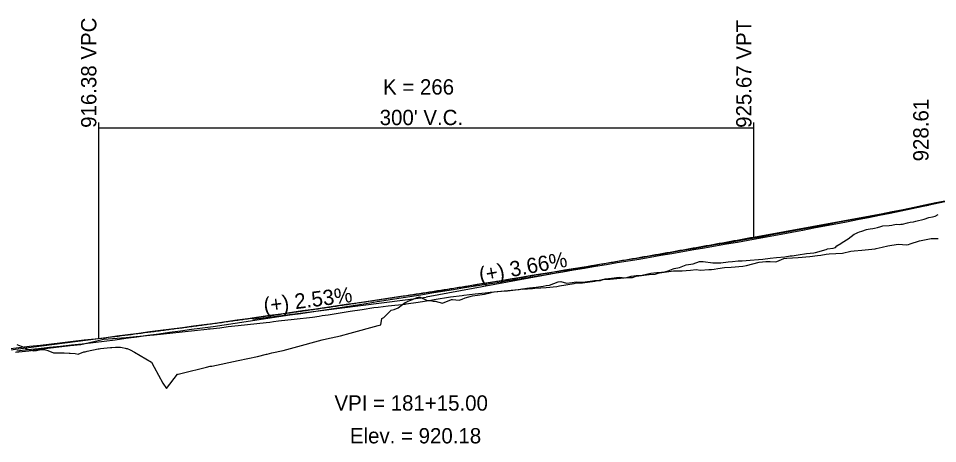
# Model space of a CAD drawing. Extents: x 1475774 to 1484571, y 1098511 to 1113011.
# Drawn here: x 1480699.3 to 1481120.2, y 1104045 to 1104239.7 of the extents above; entities that cross this region are included whole.
import ezdxf

# ---------------------------------------------------------------- set-up
doc = ezdxf.new("R2010")
doc.units = 0
for name, color, linetype in [('RD_DDB_GradeTX', 7, 'Continuous'), ('RD_DDB_PointTX', 7, 'Continuous'), ('RD_DDB_Profile_EX', 7, 'Continuous'), ('RD_DDB_Profile_Lbl', 7, 'Continuous'), ('RD_DDB_Profile_PR', 7, 'Continuous'), ('RD_DDB_StripGrade', 7, 'Continuous'), ('RD_DDB_VCLbl', 7, 'Continuous'), ('RD_Sketch2', 7, 'Continuous'), ('RD_Sketch3', 7, 'Continuous')]:
    doc.layers.add(name, color=color, linetype=linetype)

msp = doc.modelspace()

# ---------------------------------------------------------------- linework, layer by layer
at = {"layer": 'RD_DDB_GradeTX'}
for p in [(1480964.68, 1104126.56), (1480806.62, 1104102.09)]:
    msp.add_line(p, (1480885.98, 1104112.15), dxfattribs=at)
at = {"layer": 'RD_DDB_PointTX'}
msp.add_lwpolyline([(1480694.42, 1104088.43), (1480699.42, 1104089.01), (1480704.42, 1104089.59), (1480709.42, 1104090.16), (1480714.42, 1104090.75), (1480719.42, 1104091.33), (1480724.42, 1104091.91), (1480729.42, 1104092.49), (1480734.42, 1104093.06), (1480739.42, 1104093.68), (1480744.42, 1104094.34), (1480749.42, 1104095), (1480754.42, 1104095.65), (1480759.42, 1104096.31), (1480764.42, 1104096.95), (1480769.42, 1104097.61), (1480774.42, 1104098.27), (1480779.42, 1104098.93), (1480784.42, 1104099.59), (1480789.42, 1104100.24), (1480794.42, 1104100.95), (1480799.42, 1104101.66), (1480804.42, 1104102.38), (1480809.42, 1104103.09), (1480814.42, 1104103.8), (1480819.42, 1104104.51), (1480824.42, 1104105.23), (1480829.42, 1104105.94), (1480834.42, 1104106.66), (1480839.42, 1104107.39), (1480844.42, 1104108.11), (1480849.42, 1104108.84), (1480854.42, 1104109.57), (1480859.42, 1104110.3), (1480864.42, 1104111.04), (1480869.42, 1104111.77), (1480874.42, 1104112.5), (1480879.42, 1104113.22), (1480884.42, 1104113.95), (1480889.42, 1104114.7), (1480894.42, 1104115.52), (1480899.42, 1104116.34), (1480904.42, 1104117.17), (1480909.42, 1104117.99), (1480914.42, 1104118.81), (1480919.42, 1104119.63), (1480924.42, 1104120.45), (1480929.42, 1104121.28), (1480934.42, 1104122.1), (1480939.42, 1104122.92), (1480944.42, 1104123.75), (1480949.42, 1104124.57), (1480954.42, 1104125.39), (1480959.42, 1104126.21), (1480964.42, 1104127.03), (1480969.42, 1104127.85), (1480974.42, 1104128.68), (1480979.42, 1104129.5), (1480984.42, 1104130.32), (1480989.42, 1104131.15), (1480994.42, 1104132.01), (1480999.42, 1104132.87), (1481004.42, 1104133.73), (1481009.42, 1104134.59), (1481014.42, 1104135.45), (1481019.42, 1104136.31), (1481024.42, 1104137.18), (1481029.42, 1104138.04), (1481034.42, 1104138.9), (1481039.42, 1104139.77), (1481044.42, 1104140.72), (1481049.42, 1104141.66), (1481054.42, 1104142.61), (1481059.42, 1104143.55), (1481064.42, 1104144.5), (1481069.42, 1104145.44), (1481074.42, 1104146.38), (1481079.42, 1104147.33), (1481084.42, 1104148.27), (1481089.42, 1104149.24), (1481094.42, 1104150.26), (1481099.42, 1104151.28), (1481104.42, 1104152.31), (1481109.42, 1104153.33), (1481114.42, 1104154.35), (1481119.42, 1104155.38), (1481124.42, 1104156.4)], dxfattribs=at)
at = {"layer": 'RD_DDB_Profile_EX'}
msp.add_lwpolyline([(1480698.54, 1104087.54), (1480703.54, 1104088.07), (1480708.54, 1104088.6), (1480713.54, 1104089.19), (1480718.54, 1104089.72), (1480723.54, 1104090.26), (1480728.54, 1104090.8), (1480733.54, 1104091.34), (1480738.54, 1104091.96), (1480743.54, 1104092.63), (1480748.54, 1104093.31), (1480753.54, 1104093.98), (1480758.54, 1104094.66), (1480763.54, 1104095.34), (1480768.54, 1104096.02), (1480773.54, 1104096.7), (1480778.54, 1104097.38), (1480783.54, 1104098.06), (1480788.54, 1104098.73), (1480793.54, 1104099.47), (1480798.54, 1104100.22), (1480803.54, 1104100.98), (1480808.54, 1104101.71), (1480813.54, 1104102.44), (1480818.54, 1104103.18), (1480823.54, 1104103.94), (1480828.54, 1104104.69), (1480833.54, 1104105.42), (1480838.54, 1104106.14), (1480843.54, 1104106.89), (1480848.54, 1104107.63), (1480853.54, 1104108.42), (1480858.54, 1104109.26), (1480863.54, 1104110.09), (1480868.54, 1104110.85), (1480873.54, 1104111.59), (1480878.54, 1104112.36), (1480883.54, 1104113.19), (1480888.54, 1104114.02), (1480893.54, 1104114.84), (1480898.54, 1104115.67), (1480903.54, 1104116.5), (1480908.54, 1104117.27), (1480913.54, 1104118.04), (1480918.54, 1104118.86), (1480923.54, 1104119.69), (1480928.54, 1104120.52), (1480933.54, 1104121.3), (1480938.54, 1104122.07), (1480943.54, 1104122.89), (1480948.54, 1104123.73), (1480953.54, 1104124.56), (1480958.54, 1104125.4), (1480963.54, 1104126.23), (1480968.54, 1104127.07), (1480973.54, 1104127.9), (1480978.54, 1104128.74), (1480983.54, 1104129.57), (1480988.54, 1104130.4), (1480993.54, 1104131.27), (1480998.54, 1104132.14), (1481003.54, 1104133.02), (1481008.54, 1104133.88), (1481013.54, 1104134.72), (1481018.54, 1104135.58), (1481023.54, 1104136.46), (1481028.54, 1104137.33), (1481033.54, 1104138.2), (1481038.54, 1104139.04), (1481043.54, 1104139.98), (1481048.54, 1104140.93), (1481053.54, 1104141.89), (1481058.54, 1104142.85), (1481063.54, 1104143.79), (1481068.54, 1104144.74), (1481073.54, 1104145.7), (1481078.54, 1104146.66), (1481083.54, 1104147.61), (1481088.54, 1104148.56), (1481093.54, 1104149.59), (1481098.54, 1104150.62), (1481103.54, 1104151.66), (1481108.54, 1104152.7), (1481113.54, 1104153.76), (1481118.54, 1104154.8), (1481123.54, 1104155.84)], dxfattribs=at)
at = {"layer": 'RD_DDB_Profile_PR'}
for p, q in [((1481035.98, 1104139.62), (1481116.05, 1104154.28)), ((1480660.98, 1104083.65), (1480735.98, 1104093.15))]:
    msp.add_line(p, q, dxfattribs=at)
msp.add_spline([(1480735.98, 1104093.15), (1480741.98, 1104093.91), (1480747.98, 1104094.68), (1480753.98, 1104095.46), (1480759.98, 1104096.24), (1480765.98, 1104097.03), (1480771.98, 1104097.83), (1480777.98, 1104098.63), (1480783.98, 1104099.44), (1480789.98, 1104100.26), (1480795.98, 1104101.09), (1480801.98, 1104101.92), (1480807.98, 1104102.75), (1480813.98, 1104103.6), (1480819.98, 1104104.45), (1480825.98, 1104105.31), (1480831.98, 1104106.17), (1480837.98, 1104107.05), (1480843.98, 1104107.92), (1480849.98, 1104108.81), (1480855.98, 1104109.7), (1480861.98, 1104110.6), (1480867.98, 1104111.51), (1480873.98, 1104112.42), (1480879.98, 1104113.34), (1480885.98, 1104114.26), (1480891.98, 1104115.2), (1480897.98, 1104116.14), (1480903.98, 1104117.08), (1480909.98, 1104118.04), (1480915.98, 1104119), (1480921.98, 1104119.96), (1480927.98, 1104120.94), (1480933.98, 1104121.92), (1480939.98, 1104122.9), (1480945.98, 1104123.9), (1480951.98, 1104124.9), (1480957.98, 1104125.91), (1480963.98, 1104126.92), (1480969.98, 1104127.94), (1480975.98, 1104128.97), (1480981.98, 1104130), (1480987.98, 1104131.04), (1480993.98, 1104132.09), (1480999.98, 1104133.15), (1481005.98, 1104134.21), (1481011.98, 1104135.28), (1481017.98, 1104136.35), (1481023.98, 1104137.43), (1481029.98, 1104138.52), (1481035.98, 1104139.62)], degree=3, dxfattribs=at)
at = {"layer": 'RD_DDB_VCLbl'}
for p, q in [((1480735.98, 1104192.12), (1480735.98, 1104093.15)), ((1480735.98, 1104189.62), (1481035.98, 1104189.62)), ((1481035.98, 1104192.12), (1481035.98, 1104139.62))]:
    msp.add_line(p, q, dxfattribs=at)
at = {"layer": 'RD_Sketch2'}
msp.add_lwpolyline([(1480697.89, 1104086.92), (1480704.09, 1104087.6), (1480710.18, 1104088.39), (1480716.52, 1104089.21), (1480723, 1104089.92), (1480727.93, 1104090.47), (1480735.83, 1104092.31), (1480738.18, 1104092.84), (1480748.65, 1104093.66), (1480759.41, 1104094.63), (1480761.47, 1104094.89), (1480774.3, 1104096.26), (1480785.58, 1104097.48), (1480786.11, 1104097.54), (1480787.12, 1104097.65), (1480791.5, 1104098.12), (1480795.27, 1104098.62), (1480799.94, 1104099.13), (1480812.76, 1104100.54), (1480814.4, 1104100.72), (1480816.05, 1104100.93), (1480818.44, 1104101.24), (1480825.59, 1104102.05), (1480833.97, 1104103), (1480837.03, 1104103.45), (1480838.41, 1104103.65), (1480841.16, 1104104.05), (1480844.73, 1104104.64), (1480851.23, 1104105.62), (1480856.71, 1104106.44), (1480862.06, 1104107.36), (1480864.06, 1104107.58), (1480868.57, 1104108.08), (1480876.33, 1104108.95), (1480876.88, 1104109.03), (1480882.36, 1104109.83), (1480888.13, 1104110.76), (1480889.7, 1104111.01), (1480897.2, 1104112.22), (1480902.52, 1104112.9), (1480903.29, 1104113), (1480908.39, 1104113.64), (1480913.07, 1104114.11), (1480915.35, 1104114.33), (1480920.16, 1104114.8), (1480928.17, 1104115.59), (1480928.57, 1104115.63), (1480929.88, 1104115.84), (1480930.31, 1104115.76), (1480934.68, 1104116.1), (1480935.74, 1104116.18), (1480938.57, 1104116.4), (1480940.99, 1104116.59), (1480945.9, 1104116.98), (1480947.13, 1104117.26), (1480953.82, 1104118.31), (1480954.9, 1104118.65), (1480957.55, 1104118.63), (1480963.28, 1104119.47), (1480966.64, 1104120.13), (1480970.33, 1104120.41), (1480973.37, 1104120.66), (1480978.32, 1104121.04), (1480979.46, 1104121.03), (1480980.54, 1104121.03), (1480982.25, 1104121.66), (1480988.18, 1104122.47), (1480990.89, 1104122.58), (1480992.28, 1104123.05), (1480992.92, 1104123.27), (1480997.21, 1104123.86), (1480999.28, 1104124.23), (1481003.24, 1104124.1), (1481005.11, 1104124.29), (1481007.13, 1104124.49), (1481009.7, 1104124.78), (1481011.69, 1104124.43), (1481015.53, 1104124.79), (1481016.7, 1104124.71), (1481017.93, 1104124.96), (1481019.58, 1104125.29), (1481022.68, 1104125.68), (1481025.75, 1104125.77), (1481030.97, 1104126.31), (1481032.65, 1104126.53), (1481038.56, 1104128.16), (1481041.62, 1104128.45), (1481043.58, 1104128.38), (1481046.02, 1104128.3), (1481046.58, 1104128.38), (1481049.78, 1104129.74), (1481051.19, 1104129.97), (1481056.4, 1104130.32), (1481061.65, 1104130.78), (1481065.29, 1104131.18), (1481066.74, 1104131.37), (1481069.22, 1104131.79), (1481070.53, 1104132.01), (1481076.65, 1104132.27), (1481080.49, 1104133.23), (1481082.04, 1104133.33), (1481085.53, 1104133.56), (1481091.56, 1104134.27), (1481092.13, 1104134.37), (1481094.87, 1104135.01), (1481097.38, 1104135.6), (1481102.21, 1104136.32), (1481106.07, 1104136.02), (1481106.89, 1104136.18), (1481107.69, 1104136.47), (1481111.87, 1104137.93), (1481117.28, 1104138.95), (1481120.51, 1104138.91)], dxfattribs=at)
at = {"layer": 'RD_Sketch3'}
msp.add_lwpolyline([(1480698.49, 1104090.45), (1480699.29, 1104090.14), (1480701.07, 1104089.55), (1480703.33, 1104088.36), (1480706.41, 1104087.51), (1480707.52, 1104087.71), (1480709.62, 1104088.11), (1480710.18, 1104088.12), (1480710.79, 1104088.12), (1480711.76, 1104088.03), (1480712.76, 1104087.65), (1480715.3, 1104086.66), (1480718.09, 1104086.61), (1480720.31, 1104086.55), (1480722.54, 1104086.51), (1480723, 1104086.47), (1480725.32, 1104086.31), (1480726.67, 1104085.97), (1480729.18, 1104087.03), (1480729.91, 1104087.09), (1480730.81, 1104087.31), (1480735.83, 1104088.4), (1480736.23, 1104088.48), (1480736.87, 1104088.54), (1480741.44, 1104089.07), (1480742, 1104089.09), (1480743.82, 1104089.18), (1480745.27, 1104089.25), (1480745.96, 1104089.19), (1480746.84, 1104089.03), (1480748.1, 1104088.69), (1480748.65, 1104088.63), (1480749.1, 1104088.58), (1480750.44, 1104087.99), (1480752.43, 1104086.92), (1480760.27, 1104082.39), (1480761.47, 1104080.11), (1480765.35, 1104072.74), (1480767.07, 1104070.22), (1480772.09, 1104076.8), (1480772.48, 1104076.83), (1480774.3, 1104077.28), (1480785.47, 1104080.09), (1480787.12, 1104080.43), (1480787.82, 1104080.58), (1480799.94, 1104083.12), (1480808.74, 1104084.97), (1480812.84, 1104085.97), (1480813.16, 1104086.04), (1480815.37, 1104086.65), (1480820.55, 1104087.71), (1480825.59, 1104089.07), (1480838.41, 1104092.56), (1480840.32, 1104093.08), (1480846.72, 1104094.37), (1480851.23, 1104095.59), (1480864.06, 1104099.07), (1480865.28, 1104099.4), (1480865.7, 1104102.28), (1480866.69, 1104102.76), (1480870, 1104106.21), (1480871.3, 1104106.47), (1480873.21, 1104107.28), (1480875.11, 1104108.78), (1480876.42, 1104109.61), (1480876.88, 1104109.84), (1480878.09, 1104110.44), (1480878.92, 1104110.72), (1480881.83, 1104111.98), (1480882.98, 1104112.31), (1480886.53, 1104110.56), (1480887.11, 1104110.55), (1480887.86, 1104110.57), (1480889.25, 1104110.25), (1480889.7, 1104110.26), (1480890.2, 1104110.27), (1480893.43, 1104109.36), (1480897.6, 1104111.02), (1480898.04, 1104111.06), (1480901.06, 1104110.67), (1480902.52, 1104111.24), (1480903.82, 1104111.73), (1480907.26, 1104112.74), (1480909.51, 1104112.95), (1480912.8, 1104113.52), (1480915.35, 1104114.13), (1480916.25, 1104114.35), (1480917.19, 1104114.57), (1480920.52, 1104114.81), (1480923.32, 1104115.05), (1480926.9, 1104115.45), (1480928.17, 1104115.56), (1480928.51, 1104115.6), (1480932.04, 1104116.15), (1480933.26, 1104116.3), (1480936.33, 1104116.75), (1480939.59, 1104117.19), (1480940.99, 1104117.38), (1480942.52, 1104117.59), (1480946.4, 1104119.12), (1480947.63, 1104119.28), (1480950.35, 1104118.51), (1480952.81, 1104118.85), (1480953.82, 1104118.99), (1480955.02, 1104119.16), (1480957.65, 1104119.04), (1480961.14, 1104119.45), (1480963.08, 1104119.71), (1480965.77, 1104119.69), (1480966.64, 1104120.01), (1480968.02, 1104120.52), (1480970.88, 1104120.83), (1480974.4, 1104121.32), (1480977.11, 1104120.98), (1480977.94, 1104121.1), (1480979.46, 1104121.57), (1480979.95, 1104121.72), (1480982.18, 1104122.04), (1480984.99, 1104122.15), (1480988.86, 1104123.1), (1480991.61, 1104123.32), (1480992.28, 1104123.4), (1480995.33, 1104123.75), (1480996.85, 1104124.12), (1480999.07, 1104125.09), (1480999.61, 1104125.17), (1481001.98, 1104125.62), (1481005.11, 1104126.95), (1481008.25, 1104127.42), (1481011.19, 1104128.38), (1481012.84, 1104128.42), (1481017.3, 1104127.81), (1481017.93, 1104127.8), (1481020.95, 1104127.76), (1481024.33, 1104128.32), (1481026.22, 1104128.46), (1481028.92, 1104128.66), (1481030.75, 1104128.78), (1481034.45, 1104129.02), (1481038.16, 1104129.3), (1481040.18, 1104129.52), (1481043.58, 1104129.89), (1481046.39, 1104130.19), (1481050.23, 1104130.62), (1481052.69, 1104130.98), (1481053.6, 1104131.08), (1481056.4, 1104131.5), (1481060.14, 1104132.05), (1481063.56, 1104132.44), (1481064.27, 1104132.52), (1481069.22, 1104133.99), (1481069.87, 1104134.18), (1481072.38, 1104134.49), (1481073.41, 1104134.85), (1481074.13, 1104135.58), (1481075.94, 1104136.6), (1481076.53, 1104137.09), (1481079.31, 1104138.85), (1481082.04, 1104140.93), (1481082.78, 1104141.29), (1481083.7, 1104141.74), (1481084.41, 1104141.98), (1481085.5, 1104142.27), (1481087.6, 1104143.07), (1481088.35, 1104143.24), (1481089.33, 1104143.33), (1481090.49, 1104143.53), (1481091.38, 1104143.64), (1481092.64, 1104143.97), (1481094.28, 1104144.47), (1481095.16, 1104144.74), (1481098.03, 1104144.89), (1481099.22, 1104145), (1481101.21, 1104145.45), (1481102.72, 1104145.4), (1481103.35, 1104145.51), (1481104.17, 1104145.59), (1481106.5, 1104146.09), (1481107.69, 1104146.5), (1481109.12, 1104146.6), (1481110.27, 1104146.84), (1481114.07, 1104147.8), (1481116.2, 1104148.58), (1481117.83, 1104148.9), (1481119.03, 1104149.26), (1481120.51, 1104149.96)], dxfattribs=at)

# ---------------------------------------------------------------- texts
at = {"layer": 'RD_DDB_GradeTX'}
for s, rotation, p in [('(+) 3.66%', 10.3785, (1480910.88, 1104118.74)), ('(+) 2.53%', 7.2188, (1480811.99, 1104104.79))]:
    msp.add_text(s, height=7, rotation=rotation, dxfattribs=at).set_placement(p)
at = {"layer": 'RD_DDB_Profile_Lbl'}
msp.add_text('928.61', height=7, rotation=90, dxfattribs=at).set_placement((1481116.05, 1104174.28))
for s, p in [('VPI = 181+15.00', (1480844.02, 1104060.15)), ('Elev. = 920.18', (1480851.09, 1104045.15))]:
    msp.add_text(s, height=7, dxfattribs=at).set_placement(p)
at = {"layer": 'RD_DDB_StripGrade'}
for s, p in [('916.38 VPC', (1480734.98, 1104189.62)), ('925.67 VPT', (1481034.98, 1104189.62))]:
    msp.add_text(s, height=7, rotation=90, dxfattribs=at).set_placement(p)
at = {"layer": 'RD_DDB_VCLbl'}
for s, p in [('K = 266', (1480866.26, 1104204.87)), ("300' V.C.", (1480864.73, 1104190.87))]:
    msp.add_text(s, height=7, dxfattribs=at).set_placement(p)

doc.saveas('drawing.dxf')
